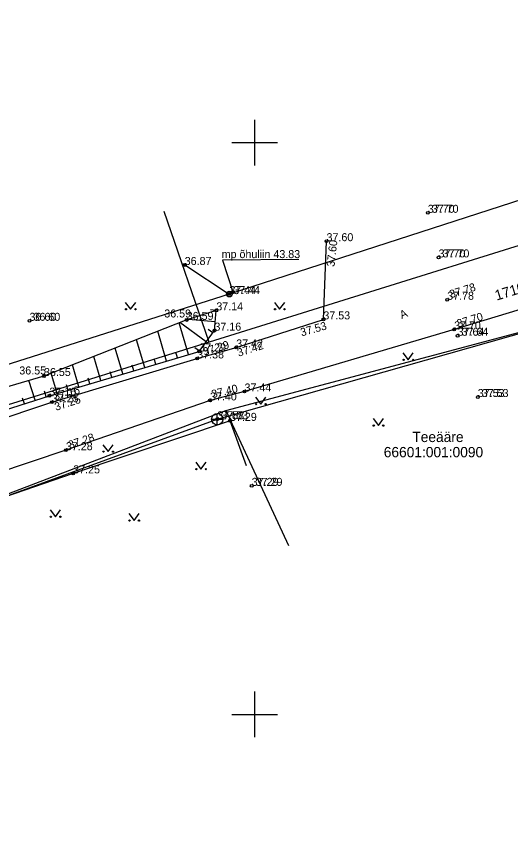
# Model space of a CAD drawing. Extents: x 627548 to 628052, y 6467984 to 6468802.
# Drawn here: x 627679.2 to 627722.4, y 6468388.4 to 6468461 of the extents above; entities that cross this region are included whole.
import ezdxf

# ---------------------------------------------------------------- set-up
doc = ezdxf.new("R2010")
doc.units = 0
for name, color, linetype in [('ABIJOONIS', 7, 'Continuous'), ('AED', 7, 'Continuous'), ('HALJASTUS', 7, 'Continuous'), ('KKAEV', 7, 'Continuous'), ('KORGUS-EH2000', 7, 'Continuous'), ('KTRASS', 7, 'Continuous'), ('MOOTKORG-EH2000', 7, 'Continuous'), ('MOOTMPUNKT', 7, 'Continuous'), ('MPOHULIIN', 7, 'Continuous'), ('PIIR', 7, 'Continuous'), ('POST', 7, 'Continuous'), ('RELJEEF', 7, 'Continuous'), ('SIOHULIIN', 7, 'Continuous'), ('TEE', 7, 'Continuous'), ('VORK', 7, 'Continuous')]:
    doc.layers.add(name, color=color, linetype=linetype)

msp = doc.modelspace()

# ---------------------------------------------------------------- linework, layer by layer
at = {"layer": 'ABIJOONIS'}
msp.add_lwpolyline([(627703.874, 6468439.765), (627697.202, 6468439.726), (627698.133, 6468436.862)], dxfattribs=at)
at = {"layer": 'AED'}
msp.add_lwpolyline([(627699.286, 6468421.733), (627697.85, 6468425.664), (627684.125, 6468421.07), (627675.531, 6468418.124)], dxfattribs=at)
at = {"layer": 'HALJASTUS'}
for p, q in [((627688.683, 6468436.027), (627689.147, 6468435.42)), ((627689.147, 6468435.42), (627689.592, 6468436.027)), ((627701.73, 6468436.027), (627702.193, 6468435.42)), ((627702.193, 6468435.42), (627702.639, 6468436.027)), ((627712.986, 6468431.603), (627713.449, 6468430.996)), ((627713.449, 6468430.996), (627713.895, 6468431.603)), ((627700.077, 6468427.734), (627700.54, 6468427.127)), ((627700.54, 6468427.127), (627700.986, 6468427.734)), ((627710.37, 6468425.856), (627710.833, 6468425.249)), ((627710.833, 6468425.249), (627711.279, 6468425.856)), ((627686.713, 6468423.58), (627687.176, 6468422.973)), ((627687.176, 6468422.973), (627687.622, 6468423.58)), ((627694.845, 6468422.044), (627695.308, 6468421.437)), ((627695.308, 6468421.437), (627695.754, 6468422.044)), ((627682.107, 6468417.89), (627682.57, 6468417.283)), ((627682.57, 6468417.283), (627683.016, 6468417.89)), ((627688.988, 6468417.549), (627689.451, 6468416.942)), ((627689.451, 6468416.942), (627689.897, 6468417.549))]:
    msp.add_line(p, q, dxfattribs=at)
for centre in [(627688.746, 6468435.42), (627689.574, 6468435.42), (627701.792, 6468435.42), (627702.621, 6468435.42), (627713.048, 6468430.996), (627713.877, 6468430.996), (627700.139, 6468427.127), (627700.968, 6468427.127), (627710.432, 6468425.249), (627711.261, 6468425.249), (627686.775, 6468422.973), (627687.604, 6468422.973), (627694.907, 6468421.437), (627695.736, 6468421.437), (627682.169, 6468417.283), (627682.998, 6468417.283), (627689.05, 6468416.942), (627689.879, 6468416.942)]:
    msp.add_circle(centre, 0.055, dxfattribs=at)
at = {"layer": 'KKAEV'}
for p, q in [((627696.734, 6468425.303), (627696.734, 6468426.303)), ((627696.234, 6468425.803), (627697.234, 6468425.803))]:
    msp.add_line(p, q, dxfattribs=at)
msp.add_circle((627696.734, 6468425.803), 0.5, dxfattribs=at)
at = {"layer": 'KTRASS'}
msp.add_lwpolyline([(627653.907, 6468388.368), (627643.967, 6468406.571), (627696.734, 6468425.803), (627727.929, 6468434.638), (627765.976, 6468446.513), (627766.878, 6468443.315), (627768.149, 6468438.807)], dxfattribs=at)
at = {"layer": 'MOOTMPUNKT'}
for centre in [(627715.159, 6468443.857), (627706.299, 6468441.373), (627716.105, 6468439.955), (627693.884, 6468439.295), (627697.787, 6468436.749), (627698.112, 6468436.926), (627716.86, 6468436.251), (627696.651, 6468435.326), (627680.299, 6468434.413), (627694.06, 6468434.488), (627706.02, 6468434.537), (627696.486, 6468433.552), (627717.465, 6468433.665), (627717.773, 6468433.106), (627698.392, 6468432.085), (627695.156, 6468431.738), (627694.979, 6468431.122), (627681.566, 6468429.584), (627682.037, 6468427.865), (627699.12, 6468428.233), (627719.537, 6468427.746), (627682.248, 6468427.296), (627696.098, 6468427.452), (627696.734, 6468425.803), (627697.85, 6468425.664), (627683.485, 6468423.1), (627684.125, 6468421.07), (627699.749, 6468419.98)]:
    msp.add_circle(centre, 0.125, dxfattribs=at)
at = {"layer": 'MPOHULIIN'}
for points in [[(627750.093, 6468453.636), (627697.787, 6468436.749)], [(627697.787, 6468436.749), (627649.965, 6468421.549)]]:
    msp.add_lwpolyline(points, dxfattribs=at)
at = {"layer": 'PIIR'}
for p, q in [((627696.02, 6468432.54), (627692.087, 6468443.971)), ((627730.27, 6468443.22), (627696.02, 6468432.54)), ((627697.47, 6468426.57), (627729.69, 6468435.15)), ((627696.02, 6468432.54), (627664.7, 6468422.8)), ((627658.9, 6468411.81), (627697.47, 6468426.57)), ((627697.47, 6468426.57), (627702.962, 6468414.765))]:
    msp.add_line(p, q, dxfattribs=at)
at = {"layer": 'POST'}
msp.add_lwpolyline([(627693.884, 6468439.295), (627697.787, 6468436.749)], dxfattribs=at)
for centre, radius in [((627693.884, 6468439.295), 0.125), ((627693.884, 6468439.295), 0.117), ((627693.884, 6468439.295), 0.109), ((627693.884, 6468439.295), 0.102), ((627693.884, 6468439.295), 0.0938), ((627693.884, 6468439.295), 0.086), ((627693.884, 6468439.295), 0.0782), ((627693.884, 6468439.295), 0.0704), ((627693.884, 6468439.295), 0.0626), ((627693.884, 6468439.295), 0.0548), ((627693.884, 6468439.295), 0.047), ((627693.884, 6468439.295), 0.0392), ((627693.884, 6468439.295), 0.0314), ((627693.884, 6468439.295), 0.0236), ((627693.884, 6468439.295), 0.0158), ((627693.884, 6468439.295), 0.00798), ((627693.884, 6468439.295), 0.000186), ((627697.787, 6468436.749), 0.25), ((627697.787, 6468436.749), 0.0234)]:
    msp.add_circle(centre, radius, dxfattribs=at)
at = {"layer": 'RELJEEF'}
for p, q in [((627696.65, 6468435.319), (627696.153, 6468435.366)), ((627695.762, 6468432.564), (627693.459, 6468434.252)), ((627696.558, 6468434.324), (627694.223, 6468434.541)), ((627694.22, 6468431.462), (627693.403, 6468434.23)), ((627696.353, 6468433.371), (627695.95, 6468433.666)), ((627692.302, 6468430.895), (627691.534, 6468433.497)), ((627690.384, 6468430.329), (627689.665, 6468432.763)), ((627688.466, 6468429.763), (627687.797, 6468432.03)), ((627693.261, 6468431.179), (627693.12, 6468431.658)), ((627695.17, 6468431.758), (627694.767, 6468432.053)), ((627686.548, 6468429.197), (627685.928, 6468431.296)), ((627691.343, 6468430.612), (627691.201, 6468431.092)), ((627684.629, 6468428.63), (627684.059, 6468430.563)), ((627687.507, 6468429.48), (627687.365, 6468429.959)), ((627689.425, 6468430.046), (627689.283, 6468430.526)), ((627680.801, 6468427.471), (627680.25, 6468429.198)), ((627682.711, 6468428.064), (627682.19, 6468429.829)), ((627685.589, 6468428.913), (627685.447, 6468429.393)), ((627683.67, 6468428.347), (627683.529, 6468428.827)), ((627681.754, 6468427.775), (627681.602, 6468428.251)), ((627679.849, 6468427.167), (627679.697, 6468427.643))]:
    msp.add_line(p, q, dxfattribs=at)
for points in [[(627696.651, 6468435.326), (627694.06, 6468434.488), (627681.566, 6468429.584), (627666.141, 6468425.06), (627665.082, 6468422.456)], [(627665.082, 6468422.456), (627682.037, 6468427.865), (627695.156, 6468431.738), (627696.486, 6468433.552), (627696.651, 6468435.326)]]:
    msp.add_lwpolyline(points, dxfattribs=at)
at = {"layer": 'SIOHULIIN'}
for points in [[(627750.093, 6468453.636), (627697.787, 6468436.749)], [(627697.787, 6468436.749), (627649.965, 6468421.549)]]:
    msp.add_lwpolyline(points, dxfattribs=at)
at = {"layer": 'TEE'}
for points in [[(627796.263, 6468461.011), (627787.58, 6468457.698), (627775.784, 6468453.617), (627755.708, 6468445.797), (627743.362, 6468441.806), (627728.433, 6468436.983), (627717.465, 6468433.665), (627699.12, 6468428.233), (627696.098, 6468427.452), (627683.485, 6468423.1), (627674.185, 6468419.981), (627673.482, 6468419.039), (627673.355, 6468417.806)], [(627641.613, 6468422.918), (627643.502, 6468420.588), (627645.892, 6468418.897), (627648.756, 6468417.722), (627652.03, 6468417.397), (627656.357, 6468418.393), (627665.677, 6468421.76), (627682.248, 6468427.296), (627694.979, 6468431.122), (627698.392, 6468432.085), (627706.02, 6468434.537), (627706.299, 6468441.373)]]:
    msp.add_lwpolyline(points, dxfattribs=at)
at = {"layer": 'VORK'}
for p, q in [((627700, 6468452), (627700, 6468448)), ((627698, 6468450), (627702, 6468450)), ((627700, 6468402), (627700, 6468398)), ((627698, 6468400), (627702, 6468400))]:
    msp.add_line(p, q, dxfattribs=at)

# ---------------------------------------------------------------- texts
at = {"layer": 'ABIJOONIS'}
msp.add_text('mp õhuliin 43.83', height=0.7, dxfattribs=at).set_placement((627697.12, 6468439.894))
at = {"layer": 'KORGUS-EH2000'}
for s, p in [('37.70', (627715.509, 6468443.857)), ('37.70', (627716.455, 6468439.955)), ('37.44', (627698.137, 6468436.749)), ('36.60', (627680.649, 6468434.413)), ('36.59', (627692.095, 6468434.704)), ('37.64', (627718.123, 6468433.106)), ('36.55', (627679.407, 6468429.721)), ('37.53', (627719.887, 6468427.746)), ('37.53', (627697.084, 6468425.803)), ('37.29', (627700.099, 6468419.98))]:
    msp.add_text(s, height=0.7, dxfattribs=at).set_placement(p)
for s, rotation, p in [('37.60', 83.44902, (627706.988, 6468439.11)), ('37.78', 17.3249, (627717.18, 6468436.379)), ('37.70', 16.96887, (627717.817, 6468433.813)), ('37.53', 15.68459, (627704.119, 6468433.046)), ('37.29', 17.03333, (627695.602, 6468431.352)), ('37.42', 17.53937, (627698.602, 6468431.266)), ('37.16', 15.34265, (627682.512, 6468427.448)), ('37.40', 13.55931, (627696.314, 6468427.646)), ('37.25', 18.04495, (627682.62, 6468426.536)), ('37.28', 18.67003, (627683.83, 6468423.2))]:
    msp.add_text(s, height=0.7, rotation=rotation, dxfattribs=at).set_placement(p)
at = {"layer": 'MOOTKORG-EH2000'}
for s, p in [('37.70', (627715.159, 6468443.857)), ('37.60', (627706.299, 6468441.373)), ('37.70', (627716.105, 6468439.955)), ('36.87', (627693.884, 6468439.295)), ('37.44', (627697.787, 6468436.749)), ('37.78', (627716.86, 6468436.251)), ('37.14', (627696.651, 6468435.326)), ('36.60', (627680.299, 6468434.413)), ('36.59', (627694.06, 6468434.488)), ('37.53', (627706.02, 6468434.537)), ('37.16', (627696.486, 6468433.552)), ('37.70', (627717.465, 6468433.665)), ('37.64', (627717.773, 6468433.106)), ('37.42', (627698.392, 6468432.085)), ('37.29', (627695.156, 6468431.738)), ('37.38', (627694.979, 6468431.122)), ('36.55', (627681.566, 6468429.584)), ('37.16', (627682.037, 6468427.865)), ('37.44', (627699.12, 6468428.233)), ('37.53', (627719.537, 6468427.746)), ('37.25', (627682.248, 6468427.296)), ('37.40', (627696.098, 6468427.452)), ('37.53', (627696.734, 6468425.803)), ('37.29', (627697.85, 6468425.664)), ('37.28', (627683.485, 6468423.1)), ('37.25', (627684.125, 6468421.07)), ('37.29', (627699.749, 6468419.98))]:
    msp.add_text(s, height=0.7, dxfattribs=at).set_placement(p)
at = {"layer": 'PIIR'}
msp.add_text('17101:001:0769', height=0.9, rotation=17.03041, dxfattribs=at).set_placement((627721.188, 6468436.174))
for s, p in [('Teeääre', (627713.809, 6468423.811)), ('66601:001:0090', (627711.307, 6468422.48))]:
    msp.add_text(s, height=0.9, dxfattribs=at).set_placement(p)
at = {"layer": 'TEE'}
msp.add_text('A', height=0.7, rotation=23.80727, dxfattribs=at).set_placement((627712.888, 6468434.566))

doc.saveas('drawing.dxf')
